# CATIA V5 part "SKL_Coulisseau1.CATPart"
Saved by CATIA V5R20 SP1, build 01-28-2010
Part number: SKL_Coulisseau1
Bounding box of the stored display mesh (mm): x -85 to 85, y 0 to 0, z -30 to 45
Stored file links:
  C:\Users\Nikow\Documents\IAO\Mécanisme IAO avec squelette\nsarlin\SKL_Coulisseau1.CATPart
  J:\IAO\Mecanisme_a_bielle_et_deux_coulisseaux.CATProduct
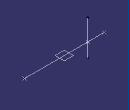
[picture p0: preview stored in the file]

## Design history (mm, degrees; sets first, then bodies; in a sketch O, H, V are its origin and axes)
Set1
  Point1 "Point_coulisseau1": linked copy from another document
  Point2: linked copy from another document
  Point3: linked copy from another document
  Plane1 "Plan_de_ref": linked copy from another document
Body1 (main body)
  Point4: (0, 0, 0), relative to Point1
  Line1 "Gliss": type PtPt, FirstPoint Point3, SecondPoint Point2
  Line2 "Pvt": type Normal, RefPoint Point4, RefSkin Plane1, Start -30, End 45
